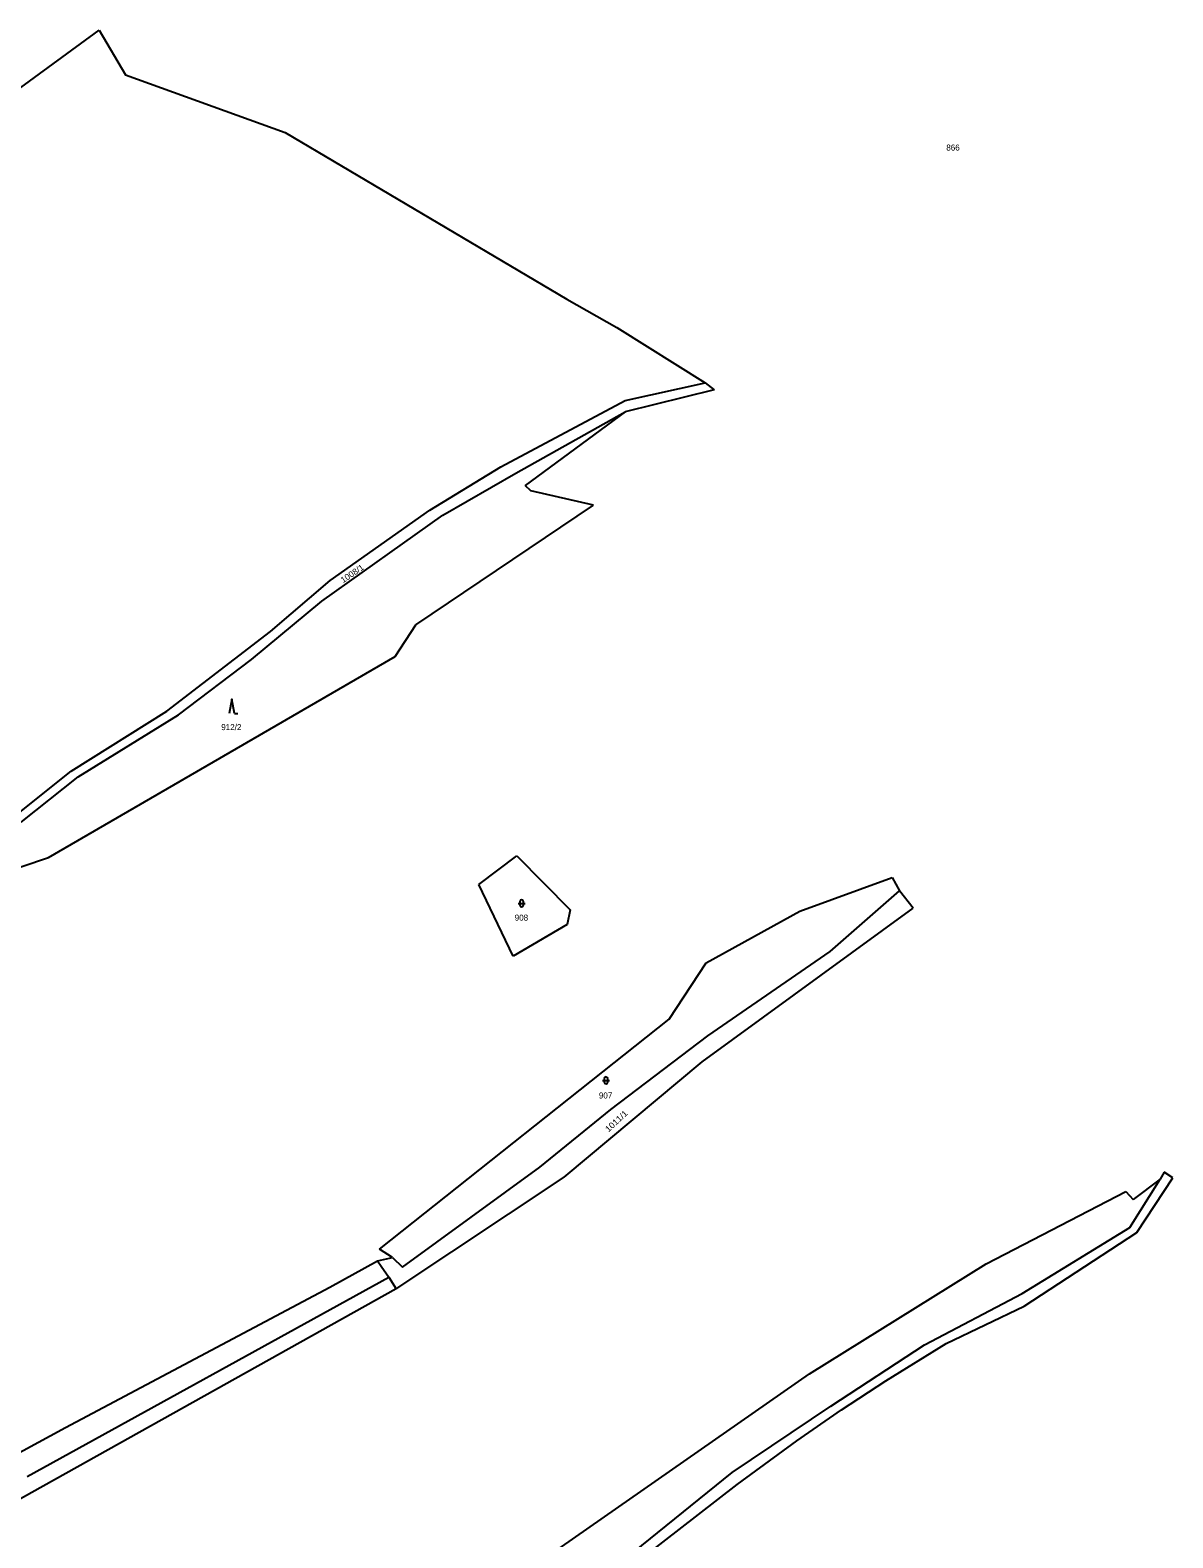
# Model space of a CAD drawing. Extents: x -744132 to -742433, y -984679 to -982287.
# Drawn here: x -743440.4 to -743118.3, y -983292.6 to -982867.8 of the extents above; entities that cross this region are included whole.
import ezdxf

# ---------------------------------------------------------------- set-up
doc = ezdxf.new("R2010")
doc.units = 0
doc.header["$LTSCALE"] = 0.68
doc.layers.add('1', color=7, linetype='Continuous', lineweight=25)
doc.layers.add('3', color=7, linetype='Continuous', lineweight=25)
doc.layers.add('2', color=7, linetype='Continuous')

msp = doc.modelspace()

# ---------------------------------------------------------------- linework, layer by layer
at = {"layer": '1'}
for p, q in [((-743448.22, -982887.75), (-743420.89, -982867.75)), ((-743420.89, -982867.75), (-743413.52, -982880.34)), ((-743413.52, -982880.34), (-743368.47, -982896.57)), ((-743368.47, -982896.57), (-743289.11, -982943.59)), ((-743289.11, -982943.59), (-743274.98, -982951.56)), ((-743274.98, -982951.56), (-743250.08, -982967.18)), ((-743272.71, -982972.13), (-743250.08, -982967.18)), ((-743247.59, -982969.11), (-743272.63, -982975.29)), ((-743250.08, -982967.18), (-743247.59, -982969.11)), ((-743307.68, -982990.85), (-743272.71, -982972.13)), ((-743303.5, -982992.6), (-743272.63, -982975.29)), ((-743272.63, -982975.29), (-743300.87, -982996.05)), ((-743327.69, -983003.06), (-743307.68, -982990.85)), ((-743324.04, -983004.45), (-743303.5, -982992.6)), ((-743299.28, -982997.58), (-743300.87, -982996.05)), ((-743281.55, -983001.6), (-743299.28, -982997.58)), ((-743355.78, -983022.8), (-743327.69, -983003.06)), ((-743331.63, -983035.29), (-743281.55, -983001.6)), ((-743358.15, -983028.69), (-743324.04, -983004.45)), ((-743372.62, -983037.23), (-743355.78, -983022.8)), ((-743377.97, -983045.07), (-743358.15, -983028.69)), ((-743401.84, -983059.68), (-743372.62, -983037.23)), ((-743337.5, -983044.29), (-743331.63, -983035.29)), ((-743435.24, -983100.86), (-743337.5, -983044.29)), ((-743398.55, -983060.69), (-743377.97, -983045.07)), ((-743428.78, -983076.59), (-743401.84, -983059.68)), ((-743426.84, -983078.17), (-743398.55, -983060.69)), ((-743443.8, -983088.48), (-743428.78, -983076.59)), ((-743442.87, -983090.98), (-743426.84, -983078.17)), ((-743467.2, -983111.76), (-743435.24, -983100.86)), ((-743313.93, -983108.54), (-743303.2, -983100.4)), ((-743303.2, -983100.4), (-743288.19, -983115.68)), ((-743304.22, -983128.66), (-743313.93, -983108.54)), ((-743223.46, -983115.99), (-743197.4, -983106.57)), ((-743197.4, -983106.57), (-743195.36, -983110.34)), ((-743214.86, -983127.41), (-743195.36, -983110.34)), ((-743191.47, -983115.21), (-743195.36, -983110.34)), ((-743288.19, -983115.68), (-743289, -983119.82)), ((-743250.93, -983158.52), (-743191.47, -983115.21)), ((-743249.84, -983130.59), (-743223.46, -983115.99)), ((-743289, -983119.82), (-743304.22, -983128.66)), ((-743260.24, -983146.5), (-743249.84, -983130.59)), ((-743249.41, -983151.2), (-743214.86, -983127.41)), ((-743341.9, -983211.3), (-743260.24, -983146.5)), ((-743276.74, -983171.92), (-743249.41, -983151.2)), ((-743289.82, -983190.99), (-743250.93, -983158.52)), ((-743296.74, -983188.12), (-743276.74, -983171.92)), ((-743335.4, -983216.33), (-743296.74, -983188.12)), ((-743120.79, -983189.58), (-743121.9, -983191.56)), ((-743118.3, -983191.14), (-743120.79, -983189.58)), ((-743337.2, -983222.45), (-743289.82, -983190.99)), ((-743130.43, -983205.18), (-743121.9, -983191.56)), ((-743121.9, -983191.56), (-743129.5, -983197.32)), ((-743128.49, -983206.59), (-743118.3, -983191.14)), ((-743170.94, -983215.43), (-743131.57, -983195.02)), ((-743131.57, -983195.02), (-743129.5, -983197.32)), ((-743160.8, -983223.79), (-743130.43, -983205.18)), ((-743160.23, -983227.31), (-743128.49, -983206.59)), ((-743338.21, -983213.58), (-743341.9, -983211.3)), ((-743355.9, -983222), (-743342.52, -983214.54)), ((-743342.52, -983214.54), (-743338.21, -983213.58)), ((-743342.52, -983214.54), (-743341.42, -983216.03)), ((-743338.21, -983213.58), (-743335.4, -983216.33)), ((-743220.7, -983246.44), (-743170.94, -983215.43)), ((-743441.23, -983275.3), (-743339.3, -983219.21)), ((-743341.42, -983216.03), (-743339.3, -983219.21)), ((-743339.3, -983219.21), (-743337.2, -983222.45)), ((-743337.2, -983222.45), (-743445.44, -983282.95)), ((-743430.41, -983261.53), (-743355.9, -983222)), ((-743188.26, -983238.26), (-743160.8, -983223.79)), ((-743182.2, -983237.85), (-743160.23, -983227.31)), ((-743214.71, -983255.51), (-743188.26, -983238.26)), ((-743199.21, -983248.42), (-743182.2, -983237.85)), ((-743294.69, -983298.01), (-743220.7, -983246.44)), ((-743211.71, -983256.59), (-743199.21, -983248.42)), ((-743242.51, -983274.2), (-743214.71, -983255.51)), ((-743224.27, -983265.33), (-743211.71, -983256.59)), ((-743477.78, -983287.24), (-743430.41, -983261.53)), ((-743241.13, -983277.61), (-743224.27, -983265.33)), ((-743280.11, -983304.56), (-743242.51, -983274.2)), ((-743280.23, -983307.88), (-743241.13, -983277.61))]:
    msp.add_line(p, q, dxfattribs=at)
at = {"layer": '3'}
for p, q in [((-743382.8, -983060.31), (-743381.804, -983060.31)), ((-743302.851, -983113.821), (-743300.849, -983113.821)), ((-743302.351, -983113.321), (-743302.351, -983114.322)), ((-743301.349, -983114.322), (-743301.349, -983113.321)), ((-743279.061, -983163.721), (-743277.059, -983163.721)), ((-743278.561, -983163.221), (-743278.561, -983164.222)), ((-743277.559, -983164.222), (-743277.559, -983163.221))]:
    msp.add_line(p, q, dxfattribs=at)
msp.add_lwpolyline([(-743382.8, -983060.31), (-743383.55, -983056.31), (-743384.3, -983060.31)], dxfattribs=at)
for centre, start, end in [((-743301.85, -983113.3209), 0, 180), ((-743301.85, -983114.3209), 180, 359.98789), ((-743278.06, -983163.2209), 0, 180), ((-743278.06, -983164.2209), 180, 359.98789)]:
    msp.add_arc(centre, 0.5, start, end, dxfattribs=at)

# ---------------------------------------------------------------- texts
at = {"layer": '2'}
for s, p in [('866', (-743182.16, -982901.685)), ('912/2', (-743386.52, -983065.005)), ('908', (-743303.81, -983118.695)), ('907', (-743280.08, -983168.815))]:
    msp.add_text(s, height=1.7, dxfattribs=at).set_placement(p)
for s, rotation, width, p in [('1008/1', 34, 1.05, (-743352.162, -983023.632)), ('1011/1', 43, 1.1, (-743277.37, -983178.41))]:
    msp.add_text(s, height=1.7, rotation=rotation, dxfattribs=dict(at, width=width)).set_placement(p)

doc.saveas('drawing.dxf')
